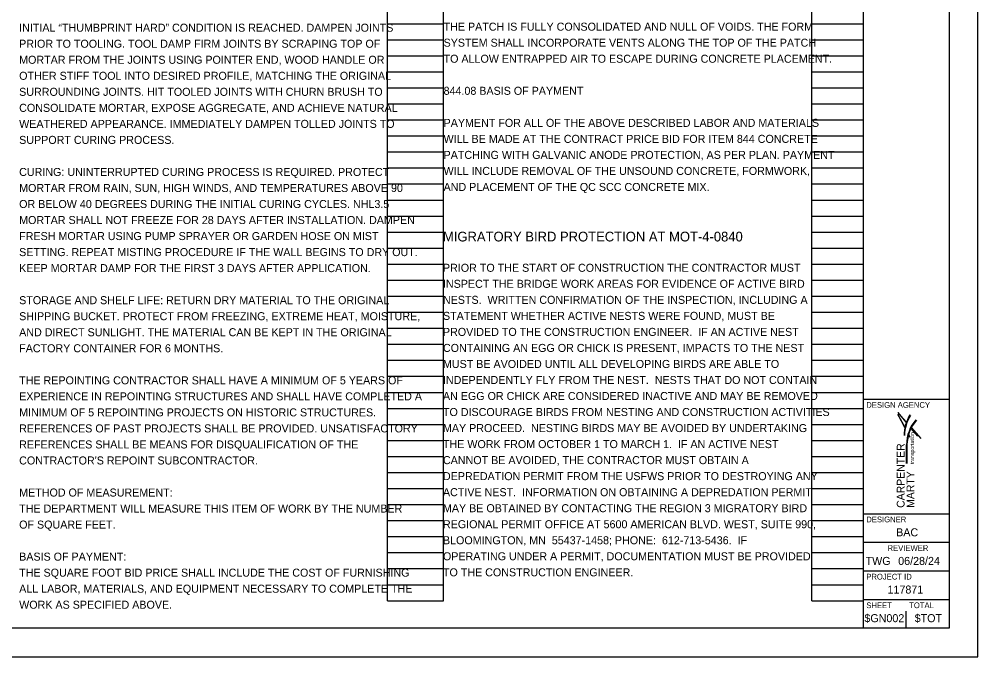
# Model space of a CAD drawing. Extents: x 0 to 59.1, y 0 to 43.6.
# Drawn here: x 17.24 to 34, y 0 to 11.14 of the extents above; entities that cross this region are included whole.
import ezdxf

# ---------------------------------------------------------------- set-up
doc = ezdxf.new("R2010")
doc.units = 0
for name, color, linetype in [('BR_P_Gen_Text', 7, 'Continuous'), ('SH_Border', 7, 'Continuous'), ('SH_Cut_Line', 7, 'Continuous'), ('SH_Data', 7, 'Continuous'), ('SH_Text', 7, 'Continuous')]:
    doc.layers.add(name, color=color, linetype=linetype)

msp = doc.modelspace()

# ---------------------------------------------------------------- linework, layer by layer
at = {"layer": 'SH_Border'}
for p, q in [((32, 0.5), (32, 21.5)), ((32, 4.5), (33.5, 4.5)), ((32, 2.5), (33.5, 2.5)), ((32, 2), (33.5, 2)), ((32, 1.5), (33.5, 1.5)), ((32, 1), (33.5, 1))]:
    msp.add_line(p, q, dxfattribs=at)
msp.add_lwpolyline([(1.5, 21.5), (33.5, 21.5), (33.5, 0.5), (1.5, 0.5)], close=True, dxfattribs=at)
at = {"layer": 'SH_Cut_Line'}
msp.add_lwpolyline([(0, 0), (34, 0), (34, 22), (0, 22)], close=True, dxfattribs=at)
at = {"layer": 'SH_Data'}
for p, q in [((23.68, 0.98), (23.68, 21.14)), ((24.66, 0.98), (24.66, 21.14)), ((31.1, 0.98), (31.1, 21.14)), ((32, 0.98), (32, 21.14)), ((23.68, 11.06), (24.66, 11.06)), ((31.1, 11.06), (32, 11.06)), ((23.68, 10.78), (24.66, 10.78)), ((31.1, 10.78), (32, 10.78)), ((23.68, 10.5), (24.66, 10.5)), ((31.1, 10.5), (32, 10.5)), ((23.68, 10.22), (24.66, 10.22)), ((31.1, 10.22), (32, 10.22)), ((23.68, 9.94), (24.66, 9.94)), ((31.1, 9.94), (32, 9.94)), ((23.68, 9.66), (24.66, 9.66)), ((31.1, 9.66), (32, 9.66)), ((23.68, 9.38), (24.66, 9.38)), ((31.1, 9.38), (32, 9.38)), ((23.68, 9.1), (24.66, 9.1)), ((31.1, 9.1), (32, 9.1)), ((23.68, 8.82), (24.66, 8.82)), ((31.1, 8.82), (32, 8.82)), ((23.68, 8.54), (24.66, 8.54)), ((31.1, 8.54), (32, 8.54)), ((23.68, 8.26), (24.66, 8.26)), ((31.1, 8.26), (32, 8.26)), ((23.68, 7.98), (24.66, 7.98)), ((31.1, 7.98), (32, 7.98)), ((23.68, 7.7), (24.66, 7.7)), ((31.1, 7.7), (32, 7.7)), ((23.68, 7.42), (24.66, 7.42)), ((31.1, 7.42), (32, 7.42)), ((23.68, 7.14), (24.66, 7.14)), ((31.1, 7.14), (32, 7.14)), ((23.68, 6.86), (24.66, 6.86)), ((31.1, 6.86), (32, 6.86)), ((23.68, 6.58), (24.66, 6.58)), ((31.1, 6.58), (32, 6.58)), ((23.68, 6.3), (24.66, 6.3)), ((31.1, 6.3), (32, 6.3)), ((23.68, 6.02), (24.66, 6.02)), ((31.1, 6.02), (32, 6.02)), ((23.68, 5.74), (24.66, 5.74)), ((31.1, 5.74), (32, 5.74)), ((23.68, 5.46), (24.66, 5.46)), ((31.1, 5.46), (32, 5.46)), ((23.68, 5.18), (24.66, 5.18)), ((31.1, 5.18), (32, 5.18)), ((23.68, 4.9), (24.66, 4.9)), ((31.1, 4.9), (32, 4.9)), ((23.68, 4.62), (24.66, 4.62)), ((31.1, 4.62), (32, 4.62)), ((23.68, 4.34), (24.66, 4.34)), ((31.1, 4.34), (32, 4.34)), ((23.68, 4.06), (24.66, 4.06)), ((31.1, 4.06), (32, 4.06)), ((23.68, 3.78), (24.66, 3.78)), ((31.1, 3.78), (32, 3.78)), ((23.68, 3.5), (24.66, 3.5)), ((31.1, 3.5), (32, 3.5)), ((32.75, 3.5), (32.75, 3.5)), ((23.68, 3.22), (24.66, 3.22)), ((31.1, 3.22), (32, 3.22)), ((23.68, 2.94), (24.66, 2.94)), ((31.1, 2.94), (32, 2.94)), ((23.68, 2.66), (24.66, 2.66)), ((31.1, 2.66), (32, 2.66)), ((23.68, 2.38), (24.66, 2.38)), ((31.1, 2.38), (32, 2.38)), ((23.68, 2.1), (24.66, 2.1)), ((31.1, 2.1), (32, 2.1)), ((23.68, 1.82), (24.66, 1.82)), ((31.1, 1.82), (32, 1.82)), ((23.68, 1.54), (24.66, 1.54)), ((31.1, 1.54), (32, 1.54)), ((23.68, 1.26), (24.66, 1.26)), ((31.1, 1.26), (32, 1.26)), ((23.68, 0.98), (24.66, 0.98)), ((31.1, 0.98), (32, 0.98)), ((32.375, 0.675), (32.375, 0.675)), ((32.75, 0.5), (32.75, 0.8))]:
    msp.add_line(p, q, dxfattribs=at)
at = {"layer": 'SH_Text'}
for p, q in [((32.721, 4.016), (32.602, 4.232)), ((32.811, 3.84), (32.79, 3.88)), ((32.82, 3.834), (32.791, 3.886)), ((32.952, 3.853), (32.834, 3.991)), ((32.839, 4.002), (33.006, 3.816)), ((32.755, 3.378), (32.755, 3.704)), ((32.762, 3.378), (32.762, 3.704))]:
    msp.add_line(p, q, dxfattribs=at)
for points in [[(32.746, 4.104), (32.601, 4.266)], [(32.601, 4.266), (32.744, 4.098)], [(32.721, 4.016), (32.602, 4.232)], [(32.602, 4.232), (32.719, 4.011)]]:
    msp.add_lwpolyline(points, dxfattribs=at)
for centre, radius, start, end in [((33.432, 3.86), 0.721, 149.5704, 179.5529), ((33.373, 3.862), 0.654, 147.1423, 179.6525), ((33.426, 3.704), 0.671, 139.2898, 180.0106), ((33.433, 3.688), 0.672, 138.5126, 178.6075)]:
    msp.add_arc(centre, radius, start, end, dxfattribs=at)

# ---------------------------------------------------------------- texts
at = {"layer": 'BR_P_Gen_Text'}
for s, p in [('THE PATCH IS FULLY CONSOLIDATED AND NULL OF VOIDS. THE FORM ', (24.66, 10.938)), ('SYSTEM SHALL INCORPORATE VENTS ALONG THE TOP OF THE PATCH ', (24.66, 10.658)), ('TO ALLOW ENTRAPPED AIR TO ESCAPE DURING CONCRETE PLACEMENT. ', (24.66, 10.378)), ('844.08 BASIS OF PAYMENT', (24.66, 9.818)), ('PAYMENT FOR ALL OF THE ABOVE DESCRIBED LABOR AND MATERIALS ', (24.66, 9.258)), ('WILL BE MADE AT THE CONTRACT PRICE BID FOR ITEM 844 CONCRETE', (24.66, 8.978)), ('PATCHING WITH GALVANIC ANODE PROTECTION, AS PER PLAN. PAYMENT', (24.66, 8.698)), ('WILL INCLUDE REMOVAL OF THE UNSOUND CONCRETE, FORMWORK,', (24.66, 8.418)), ('AND PLACEMENT OF THE QC SCC CONCRETE MIX.', (24.66, 8.138))]:
    msp.add_text(s, height=0.14, dxfattribs=at).set_placement(p)
at = {"layer": 'SH_Data'}
for s, height, p in [('DESIGN AGENCY', 0.1, (32.05, 4.35)), ('DESIGNER', 0.1, (32.05, 2.35)), ('BAC', 0.14, (32.572, 2.105)), ('REVIEWER', 0.1, (32.422, 1.85)), ('TWG', 0.14, (32.038, 1.605)), ('06/28/24', 0.14, (32.608, 1.605)), ('PROJECT ID', 0.1, (32.05, 1.35)), ('117871', 0.14, (32.421, 1.105)), ('SHEET', 0.1, (32.05, 0.85)), ('TOTAL', 0.1, (32.8, 0.85)), ('$GN002', 0.14, (32.017, 0.605)), ('$TOT', 0.14, (32.896, 0.605))]:
    msp.add_text(s, height=height, dxfattribs=at).set_placement(p)
at = {"layer": 'SH_Text'}
for s, height, p in [('INITIAL “THUMBPRINT HARD” CONDITION IS REACHED. DAMPEN JOINTS ', 0.14, (17.24, 10.92)), ('PRIOR TO TOOLING. TOOL DAMP FIRM JOINTS BY SCRAPING TOP OF ', 0.14, (17.24, 10.64)), ('MORTAR FROM THE JOINTS USING POINTER END, WOOD HANDLE OR ', 0.14, (17.24, 10.36)), ('OTHER STIFF TOOL INTO DESIRED PROFILE, MATCHING THE ORIGINAL ', 0.14, (17.24, 10.08)), ('SURROUNDING JOINTS. HIT TOOLED JOINTS WITH CHURN BRUSH TO ', 0.14, (17.24, 9.8)), ('CONSOLIDATE MORTAR, EXPOSE AGGREGATE, AND ACHIEVE NATURAL ', 0.14, (17.24, 9.52)), ('WEATHERED APPEARANCE. IMMEDIATELY DAMPEN TOLLED JOINTS TO ', 0.14, (17.24, 9.24)), ('SUPPORT CURING PROCESS.', 0.14, (17.24, 8.96)), ('CURING: UNINTERRUPTED CURING PROCESS IS REQUIRED. PROTECT ', 0.14, (17.24, 8.4)), ('MORTAR FROM RAIN, SUN, HIGH WINDS, AND TEMPERATURES ABOVE 90 ', 0.14, (17.24, 8.12)), ('OR BELOW 40 DEGREES DURING THE INITIAL CURING CYCLES. NHL3.5 ', 0.14, (17.24, 7.84)), ('MORTAR SHALL NOT FREEZE FOR 28 DAYS AFTER INSTALLATION. DAMPEN ', 0.14, (17.24, 7.56)), ('FRESH MORTAR USING PUMP SPRAYER OR GARDEN HOSE ON MIST ', 0.14, (17.24, 7.28)), ('MIGRATORY BIRD PROTECTION AT MOT-4-0840', 0.17, (24.649, 7.256)), ('SETTING. REPEAT MISTING PROCEDURE IF THE WALL BEGINS TO DRY OUT. ', 0.14, (17.24, 7)), ('KEEP MORTAR DAMP FOR THE FIRST 3 DAYS AFTER APPLICATION. ', 0.14, (17.24, 6.72)), ('PRIOR TO THE START OF CONSTRUCTION THE CONTRACTOR MUST ', 0.14, (24.649, 6.726)), ('INSPECT THE BRIDGE WORK AREAS FOR EVIDENCE OF ACTIVE BIRD ', 0.14, (24.649, 6.446)), ('STORAGE AND SHELF LIFE: RETURN DRY MATERIAL TO THE ORIGINAL ', 0.14, (17.24, 6.16)), ('NESTS.  WRITTEN CONFIRMATION OF THE INSPECTION, INCLUDING A ', 0.14, (24.649, 6.166)), ('SHIPPING BUCKET. PROTECT FROM FREEZING, EXTREME HEAT, MOISTURE, ', 0.14, (17.24, 5.88)), ('STATEMENT WHETHER ACTIVE NESTS WERE FOUND, MUST BE ', 0.14, (24.649, 5.886)), ('AND DIRECT SUNLIGHT. THE MATERIAL CAN BE KEPT IN THE ORIGINAL ', 0.14, (17.24, 5.6)), ('PROVIDED TO THE CONSTRUCTION ENGINEER.  IF AN ACTIVE NEST ', 0.14, (24.649, 5.606)), ('FACTORY CONTAINER FOR 6 MONTHS.', 0.14, (17.24, 5.32)), ('CONTAINING AN EGG OR CHICK IS PRESENT, IMPACTS TO THE NEST ', 0.14, (24.649, 5.326)), ('MUST BE AVOIDED UNTIL ALL DEVELOPING BIRDS ARE ABLE TO ', 0.14, (24.649, 5.046)), ('THE REPOINTING CONTRACTOR SHALL HAVE A MINIMUM OF 5 YEARS OF ', 0.14, (17.24, 4.76)), ('INDEPENDENTLY FLY FROM THE NEST.  NESTS THAT DO NOT CONTAIN ', 0.14, (24.649, 4.766)), ('EXPERIENCE IN REPOINTING STRUCTURES AND SHALL HAVE COMPLETED A ', 0.14, (17.24, 4.48)), ('AN EGG OR CHICK ARE CONSIDERED INACTIVE AND MAY BE REMOVED ', 0.14, (24.649, 4.486)), ('MINIMUM OF 5 REPOINTING PROJECTS ON HISTORIC STRUCTURES. ', 0.14, (17.24, 4.2)), ('TO DISCOURAGE BIRDS FROM NESTING AND CONSTRUCTION ACTIVITIES ', 0.14, (24.649, 4.206)), ('REFERENCES OF PAST PROJECTS SHALL BE PROVIDED. UNSATISFACTORY ', 0.14, (17.24, 3.92)), ('MAY PROCEED.  NESTING BIRDS MAY BE AVOIDED BY UNDERTAKING ', 0.14, (24.649, 3.926)), ('REFERENCES SHALL BE MEANS FOR DISQUALIFICATION OF THE ', 0.14, (17.24, 3.64)), ('THE WORK FROM OCTOBER 1 TO MARCH 1.  IF AN ACTIVE NEST ', 0.14, (24.649, 3.646)), ("CONTRACTOR'S REPOINT SUBCONTRACTOR.", 0.14, (17.24, 3.36)), ('CANNOT BE AVOIDED, THE CONTRACTOR MUST OBTAIN A ', 0.14, (24.649, 3.366)), ('DEPREDATION PERMIT FROM THE USFWS PRIOR TO DESTROYING ANY ', 0.14, (24.649, 3.086)), ('METHOD OF MEASUREMENT:', 0.14, (17.24, 2.8)), ('ACTIVE NEST.  INFORMATION ON OBTAINING A DEPREDATION PERMIT ', 0.14, (24.649, 2.806)), ('THE DEPARTMENT WILL MEASURE THIS ITEM OF WORK BY THE NUMBER ', 0.14, (17.24, 2.52)), ('MAY BE OBTAINED BY CONTACTING THE REGION 3 MIGRATORY BIRD ', 0.14, (24.649, 2.526)), ('OF SQUARE FEET.', 0.14, (17.24, 2.24)), ('REGIONAL PERMIT OFFICE AT 5600 AMERICAN BLVD. WEST, SUITE 990, ', 0.14, (24.649, 2.246)), ('BLOOMINGTON, MN  55437-1458; PHONE:  612-713-5436.  IF ', 0.14, (24.649, 1.966)), ('BASIS OF PAYMENT:', 0.14, (17.24, 1.68)), ('OPERATING UNDER A PERMIT, DOCUMENTATION MUST BE PROVIDED ', 0.14, (24.649, 1.686)), ('THE SQUARE FOOT BID PRICE SHALL INCLUDE THE COST OF FURNISHING ', 0.14, (17.24, 1.4)), ('TO THE CONSTRUCTION ENGINEER.', 0.14, (24.649, 1.406)), ('ALL LABOR, MATERIALS, AND EQUIPMENT NECESSARY TO COMPLETE THE ', 0.14, (17.24, 1.12)), ('WORK AS SPECIFIED ABOVE.', 0.14, (17.24, 0.84))]:
    msp.add_text(s, height=height, dxfattribs=at).set_placement(p)
for s, height, p in [('transportation', 0.06649, (32.885, 3.364)), ('CARPENTER ', 0.1367, (32.719, 2.602)), ('MARTY', 0.1367, (32.891, 2.602))]:
    msp.add_text(s, height=height, rotation=90, dxfattribs=at).set_placement(p)

doc.saveas('drawing.dxf')
